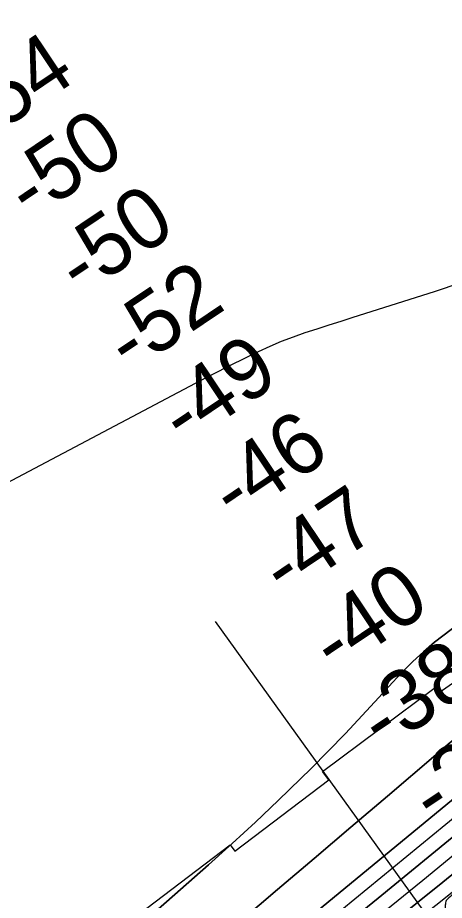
# Model space of a CAD drawing. Extents: x 3445503 to 3483459, y 540493 to 566012.
# Drawn here: x 3455212 to 3455681, y 547772 to 548741 of the extents above; entities that cross this region are included whole.
import ezdxf

# ---------------------------------------------------------------- set-up
doc = ezdxf.new("R2010")
doc.units = 0
for name, color, linetype in [('V-RIVR-EDGE', 7, 'Continuous'), ('V-RIVR-RANG', 7, 'Continuous'), ('V-RRAP-RVMT', 7, 'Continuous'), ('V-TOPO-DPTH', 7, 'Continuous'), ('V-TOPO-MAJR', 7, 'Continuous'), ('V-TOPO-MINR', 7, 'Continuous'), ('V-TOPO-WATR', 7, 'Continuous')]:
    doc.layers.add(name, color=color, linetype=linetype)

msp = doc.modelspace()

# ---------------------------------------------------------------- linework, layer by layer
at = {"layer": 'V-RIVR-EDGE'}
msp.add_spline([(3457863.5, 548983.44), (3457817.44, 548968.66), (3457802.12, 548960.7), (3457767.68, 548948.62), (3457731.48, 548932.03), (3457708.16, 548919.92), (3457702.22, 548907.76), (3457696.63, 548893.52), (3457692.42, 548877.54), (3457690.67, 548875.46), (3457688.95, 548882.77), (3457682.71, 548888), (3457675.41, 548890.1), (3457672.28, 548889.76), (3457669.15, 548886.29), (3457659.75, 548881.8), (3457640.61, 548872.81), (3457631.21, 548868.66), (3457618.34, 548865.21), (3457614.87, 548866.96), (3457612.43, 548865.23), (3457609.99, 548862.8), (3457605.46, 548857.94), (3457597.11, 548854.49), (3457585.62, 548850), (3457581.8, 548851.4), (3457575.19, 548847.94), (3457552.57, 548838.95), (3457523.35, 548829.99), (3457494.47, 548821.37), (3457480.21, 548818.28), (3457458.65, 548813.81), (3457442.3, 548807.59), (3457428.04, 548804.85), (3457409.6, 548800.37), (3457393.95, 548796.94), (3457376.56, 548792.81), (3457356.38, 548788.69), (3457340.38, 548784.9), (3457318.46, 548774.53), (3457282.62, 548763.14), (3457272.18, 548757.26), (3457258.61, 548753.12), (3457234.96, 548746.58), (3457211.64, 548735.51), (3457178.23, 548721.34), (3457160.48, 548713.04), (3457150.74, 548710.28), (3457138.92, 548708.92), (3457133.01, 548708.59), (3457123.96, 548706.52), (3457117, 548701.33), (3457101.68, 548690.94), (3457094.36, 548684), (3457088.79, 548681.58), (3457084.28, 548684.37), (3457080.1, 548683.34), (3457066.53, 548675.73), (3457054, 548670.54), (3457041.13, 548666.4), (3457034.86, 548663.64), (3457030.68, 548658.09), (3457025.11, 548655.32), (3457016.07, 548653.95), (3456990.32, 548646.02), (3456984.06, 548644.3), (3456981.27, 548639.78), (3456973.96, 548638.06), (3456959.69, 548631.49), (3456940.91, 548624.59), (3456930.12, 548621.83), (3456905.41, 548610.42), (3456885.58, 548603.17), (3456858.09, 548591.07), (3456833.02, 548577.58), (3456810.74, 548562.34), (3456791.94, 548553), (3456783.59, 548550.93), (3456781.16, 548549.55), (3456778.37, 548546.43), (3456774.19, 548544.35), (3456766.89, 548543.32), (3456746.35, 548533.29), (3456727.9, 548523.61), (3456715.72, 548515.99), (3456704.94, 548513.93), (3456691.37, 548509.44), (3456678.49, 548503.91), (3456658.31, 548495.62), (3456640.21, 548485.58), (3456625.58, 548475.89), (3456609.92, 548467.23), (3456602.96, 548463.08), (3456594.95, 548459.97), (3456583.81, 548452), (3456563.63, 548444.75), (3456558.75, 548442.33), (3456555.62, 548438.86), (3456546.91, 548431.93), (3456540.64, 548426.73), (3456538.54, 548423.26), (3456538.19, 548420.13), (3456534.36, 548419.8), (3456524.62, 548415.65), (3456518.01, 548413.58), (3456517.3, 548408.02), (3456502.35, 548404.93), (3456494.69, 548400.77), (3456476.93, 548387.61), (3456472.05, 548382.06), (3456471.68, 548376.5), (3456469.94, 548374.41), (3456465.08, 548376.86), (3456461.61, 548378.95), (3456453.6, 548374.46), (3456443.15, 548366.83), (3456436.53, 548360.59), (3456426.08, 548350.19), (3456413.2, 548341.88), (3456403.44, 548333.21), (3456403.08, 548329.39), (3456399.25, 548326.27), (3456385.32, 548316.92), (3456350.52, 548300.66), (3456316.06, 548282.33), (3456280.56, 548264.68), (3456259.31, 548249.09), (3456242.6, 548238.01), (3456225.88, 548225.88), (3456215.09, 548219.31), (3456210.92, 548218.27), (3456207.44, 548216.2), (3456199.77, 548208.91), (3456191.41, 548204.07), (3456188.27, 548196.43), (3456178.85, 548184.63), (3456172.23, 548179.43), (3456163.54, 548177.72), (3456156.58, 548173.56), (3456138.11, 548156.92), (3456111.99, 548136.82), (3456109.19, 548131.27), (3456110.92, 548125.7), (3456109.52, 548121.88), (3456101.86, 548117.38), (3456098.03, 548117.04), (3456095.96, 548120.18), (3456090.39, 548120.19), (3456087.95, 548118.11), (3456087.6, 548114.64), (3456089.67, 548110.81), (3456087.93, 548109.07), (3456081.32, 548104.22), (3456078.87, 548101.1), (3456071.9, 548092.77), (3456063.2, 548086.89), (3456046.14, 548076.5), (3456032.21, 548068.19), (3456019.67, 548059.18), (3456011.66, 548050.86), (3456004, 548047.05), (3455994.6, 548042.21), (3455984.85, 548034.59), (3455970.92, 548024.89), (3455942.36, 548001.67), (3455925.63, 547985.02), (3455888, 547951.4), (3455859.78, 547925.05), (3455831.2, 547897.31), (3455795.68, 547869.93), (3455772.69, 547850.87), (3455751.08, 547830.06), (3455739.93, 547820.36), (3455732.96, 547813.42), (3455726.69, 547806.83), (3455720.08, 547803.37), (3455716.94, 547799.21), (3455712.06, 547794.35), (3455707.19, 547792.63), (3455704.75, 547788.81), (3455704.74, 547786.03), (3455698.83, 547785), (3455689.07, 547777.72), (3455682.8, 547771.83), (3455681.75, 547766.62), (3455680.69, 547760.71), (3455676.86, 547758.63), (3455672.35, 547762.47), (3455669.56, 547759.35), (3455651.44, 547743.05), (3455646.21, 547734.72), (3455640.97, 547725), (3455639.91, 547719.44), (3455637.47, 547716.67), (3455633.3, 547714.59), (3455630.51, 547713.9), (3455628.42, 547711.13), (3455627.72, 547706.96), (3455625.97, 547701.75), (3455612.38, 547691.01), (3455586.95, 547668.82), (3455568.13, 547649.75), (3455560.11, 547641.08), (3455557.32, 547635.17), (3455554.87, 547629.27), (3455551.39, 547626.15), (3455546.52, 547624.77), (3455537.12, 547622.01), (3455533.99, 547619.24), (3455531.89, 547615.77), (3455527.7, 547608.13), (3455520.38, 547600.85), (3455503.66, 547587.68), (3455484.86, 547575.91), (3455468.84, 547563.43), (3455457, 547556.16), (3455434.72, 547543.01), (3455434.37, 547542.31), (3455433.68, 547540.92), (3455432.97, 547536.06), (3455431.22, 547533.63), (3455427.05, 547534.33), (3455422.88, 547532.95), (3455408.6, 547523.95), (3455399.2, 547518.06), (3455395.03, 547516.34), (3455391.54, 547511.83), (3455385.62, 547505.93), (3455380.74, 547503.16), (3455373.09, 547500.05), (3455368.2, 547494.15), (3455365.07, 547491.38), (3455357.76, 547487.58), (3455349.05, 547480.64), (3455342.1, 547480.31), (3455335.84, 547478.94), (3455326.78, 547472.01), (3455309.38, 547463.71), (3455304.16, 547461.98), (3455300.32, 547457.13), (3455295.45, 547452.62), (3455280.83, 547443.96), (3455275.25, 547439.11), (3455272.8, 547433.55), (3455267.93, 547430.09), (3455263.07, 547431.49), (3455257.85, 547431.51), (3455252.98, 547429.78), (3455233.48, 547416.97), (3455216.42, 547405.19), (3455207.71, 547399.3), (3455198.31, 547391.68), (3455194.13, 547387.86), (3455188.19, 547378.84), (3455176, 547368.09), (3455163.46, 547359.43), (3455159.28, 547355.62), (3455156.14, 547351.11), (3455152.66, 547349.03), (3455147.79, 547348.69), (3455143.96, 547345.92), (3455127.59, 547332.06), (3455120.97, 547327.55), (3455111.92, 547319.58), (3455097.98, 547307.8), (3455086.12, 547292.18), (3455071.5, 547281.79), (3455061.39, 547271.73), (3455057.55, 547265.14), (3455056.84, 547257.49), (3455044.3, 547250.22), (3455035.6, 547244.68), (3455007.73, 547222.5), (3454989.62, 547206.21), (3454980.21, 547197.19), (3454971.15, 547190.96), (3454953.72, 547170.14), (3454941.17, 547156.27), (3454928.29, 547146.22), (3454914.36, 547136.17), (3454901.83, 547130.29), (3454894.17, 547128.92), (3454889.64, 547123.02), (3454885.81, 547118.86), (3454878.15, 547115.75), (3454871.54, 547111.6), (3454866.65, 547105.7), (3454853.42, 547094.96), (3454836.01, 547084.92), (3454794.93, 547060.34), (3454775.78, 547046.48), (3454768.12, 547043.37), (3454766.03, 547042.33), (3454765.33, 547039.55), (3454764.63, 547037.82), (3454754.54, 547033.32), (3454745.49, 547027.78), (3454732.6, 547018.78), (3454704.75, 547000.42), (3454687.34, 546990.38), (3454661.57, 546972.72), (3454600.29, 546931.5), (3454566.5, 546905.51), (3454551.88, 546896.16), (3454544.22, 546890.62), (3454540.73, 546885.06), (3454535.49, 546878.47), (3454525.05, 546873.98), (3454519.83, 546871.21), (3454512.52, 546865.67), (3454509.04, 546863.94), (3454507.64, 546859.07), (3454504.15, 546854.22), (3454497.89, 546854.23), (3454492.32, 546851.81), (3454487.45, 546847.65), (3454481.16, 546836.89), (3454475.58, 546829.95), (3454466.53, 546824.76), (3454459.21, 546817.48), (3454445.64, 546809.52), (3454438.31, 546799.1), (3454430.29, 546789.39), (3454418.8, 546782.81), (3454407.67, 546779.71), (3454394.43, 546768.97), (3454388.5, 546760.29), (3454381.88, 546751.62), (3454374.21, 546745.03), (3454365.51, 546742.62), (3454357.85, 546735.69), (3454348.44, 546726.32), (3454339.39, 546720.09), (3454329.98, 546712.12), (3454321.62, 546705.18), (3454311.52, 546695.48), (3454298.63, 546684.73), (3454292.71, 546681.27), (3454288.89, 546681.97), (3454284.36, 546681.29), (3454283.66, 546679.21), (3454283.3, 546671.91), (3454281.2, 546667.39), (3454257.18, 546652.85), (3454236.29, 546638.3), (3454219.56, 546622.35), (3454209.11, 546612.3), (3454190.28, 546592.53), (3454175.65, 546577.96), (3454164.84, 546565.82), (3454160.32, 546563.4), (3454156.15, 546563.76), (3454151.62, 546561.34), (3454148.14, 546559.61), (3454133.51, 546546.09), (3454102.5, 546519.05), (3454096.23, 546515.94), (3454092.4, 546512.12), (3454086.13, 546505.53), (3454079.15, 546495.81), (3454067.99, 546482.98), (3454055.1, 546469.8), (3454040.81, 546455.93), (3454027.93, 546447.27), (3454012.95, 546435.14), (3453974.28, 546400.13), (3453969.39, 546393.53), (3453968.69, 546390.41), (3453968.33, 546386.93), (3453963.45, 546381.03), (3453948.12, 546364.04), (3453931.73, 546346.7), (3453925.47, 546344.63), (3453916.77, 546339.09), (3453902.84, 546331.13), (3453885.77, 546314.13), (3453868.69, 546296.1), (3453855.43, 546277.01), (3453829.27, 546239.88), (3453825.07, 546231.9), (3453825.07, 546228.77), (3453825.06, 546225.99), (3453824.36, 546224.6), (3453819.15, 546224.26), (3453815.32, 546222.88), (3453811.13, 546217.68), (3453801.36, 546202.06), (3453785.31, 546179.15), (3453759.16, 546146.89), (3453726.4, 546113.6), (3453681.81, 546074.77), (3453648.37, 546047.39), (3453614.59, 546023.84), (3453592.32, 546013.12), (3453571.08, 545999.61), (3453548.78, 545978.11), (3453537.97, 545968.06), (3453529.26, 545959.39), (3453525.44, 545959.05), (3453521.6, 545955.58), (3453517.42, 545950.73), (3453513.59, 545946.22), (3453508.71, 545944.14), (3453506.62, 545941.02), (3453505.22, 545937.89), (3453495.82, 545932.01), (3453490.94, 545926.46), (3453484.31, 545918.13), (3453481.19, 545917.79), (3453476.66, 545916.06), (3453470.04, 545909.82), (3453466.25, 545904.68)], degree=3, dxfattribs=at)
at = {"layer": 'V-RIVR-RANG'}
msp.add_line((3455826.74, 547526.64), (3455429.18, 548078.32), dxfattribs=at)
at = {"layer": 'V-RRAP-RVMT'}
for p, q in [((3455674.82, 548000.19), (3455792.37, 548082.35)), ((3455546.91, 547913.53), (3455670.75, 548005.67)), ((3455670.75, 548005.67), (3455674.82, 548000.19)), ((3455553.75, 547904.34), (3455546.91, 547913.53)), ((3455450.6, 547825.86), (3455553.75, 547904.34)), ((3455321.66, 547739.15), (3455445.16, 547833.06)), ((3455445.16, 547833.06), (3455450.6, 547825.86))]:
    msp.add_line(p, q, dxfattribs=at)
at = {"layer": 'V-TOPO-DPTH'}
for points in [[(3456856.6, 548740.67), (3456268.73, 548406.59), (3456247.79, 548392.03), (3456227.02, 548377.24), (3456206.5, 548362.08), (3455712.34, 547966.57), (3455698.61, 547955.04), (3455684.92, 547943.46), (3455671.26, 547931.85), (3455618.12, 547886.49), (3455577.89, 547852.2), (3455537.62, 547817.95), (3455497.3, 547783.76), (3455456.94, 547749.62), (3455214.72, 547545.03), (3455182.45, 547518.06), (3455149.99, 547491.33), (3455117.26, 547464.94), (3455084.33, 547438.79), (3455046.17, 547408.8), (3454993.9, 547367.98), (3454941.46, 547327.38), (3454918.49, 547309.76)], [(3456856.6, 548740.67), (3456268.73, 548406.59), (3456247.79, 548392.03), (3456227.02, 548377.24), (3456206.5, 548362.08), (3455712.34, 547966.57), (3455698.61, 547955.04), (3455684.92, 547943.46), (3455671.26, 547931.85), (3455618.12, 547886.49), (3455577.89, 547852.2), (3455537.62, 547817.95), (3455497.3, 547783.76), (3455456.94, 547749.62), (3455214.72, 547545.03), (3455182.45, 547518.06), (3455149.99, 547491.33), (3455117.26, 547464.94), (3455084.33, 547438.79), (3455046.17, 547408.8), (3454993.9, 547367.98), (3454941.46, 547327.38), (3454918.49, 547309.76)], [(3455249.33, 547659.48), (3455421.6, 547811.2), (3455447.45, 547834.36), (3455473.04, 547857.81), (3455498.22, 547881.68), (3455523.14, 547905.85), (3455533.99, 547916.56), (3455553.11, 547935.75), (3455572, 547955.16), (3455590.53, 547974.9), (3455608.84, 547994.86), (3455623.66, 548011.31), (3455634.64, 548022.96), (3455645.94, 548034.26), (3455657.73, 548045.04), (3455669.86, 548055.48), (3456187.62, 548449.08), (3456215.38, 548468.62), (3456243.11, 548488.2), (3456319.08, 548541.99), (3456382.52, 548587.52), (3456445.56, 548633.6), (3456508, 548680.48), (3456570.03, 548727.91)], [(3456570.03, 548727.91), (3456508, 548680.48), (3456445.56, 548633.6), (3456382.52, 548587.52), (3456319.08, 548541.99), (3456243.11, 548488.2), (3456215.38, 548468.62), (3456187.62, 548449.08), (3455669.86, 548055.48), (3455657.73, 548045.04), (3455645.94, 548034.26), (3455634.64, 548022.96), (3455623.66, 548011.31), (3455608.84, 547994.86), (3455590.53, 547974.9), (3455572, 547955.16), (3455553.11, 547935.75), (3455533.99, 547916.56), (3455523.14, 547905.85), (3455498.22, 547881.68), (3455473.04, 547857.81), (3455447.45, 547834.36), (3455421.6, 547811.2), (3455249.33, 547659.48)], [(3456887.15, 548729.97), (3456251.76, 548335.86), (3456250.94, 548335.31), (3456248.53, 548333.61), (3456244.09, 548330.33), (3456241.1, 548328.09), (3456238.13, 548325.81), (3456235.19, 548323.5), (3456232.27, 548321.15), (3456209.81, 548302.85), (3456195.66, 548291.35), (3456181.51, 548279.87), (3456167.33, 548268.41), (3456153.14, 548256.96), (3455823.07, 547991.16), (3455806.97, 547978.17), (3455790.88, 547965.17), (3455774.82, 547952.13), (3455758.77, 547939.08), (3455742.75, 547926.01), (3455726.73, 547912.91), (3455710.74, 547899.8), (3455694.75, 547886.67), (3455356.77, 547608.66)], [(3455356.77, 547608.66), (3455694.75, 547886.67), (3455710.74, 547899.8), (3455726.73, 547912.91), (3455742.75, 547926.01), (3455758.77, 547939.08), (3455774.82, 547952.13), (3455790.88, 547965.17), (3455806.97, 547978.17), (3455823.07, 547991.16), (3456153.14, 548256.96), (3456167.33, 548268.41), (3456181.51, 548279.87), (3456195.66, 548291.35), (3456209.81, 548302.85), (3456232.27, 548321.15), (3456235.19, 548323.5), (3456238.13, 548325.81), (3456241.1, 548328.09), (3456244.09, 548330.33), (3456248.53, 548333.61), (3456250.94, 548335.31), (3456251.76, 548335.86), (3456887.15, 548729.97)], [(3455539.36, 547718.68), (3455607.82, 547774.46), (3455703.41, 547852.68), (3455723.95, 547869.49), (3455744.5, 547886.3), (3455765.05, 547903.1), (3455785.61, 547919.9), (3455844.79, 547968.27), (3455895.2, 548008.91), (3455945.96, 548049.11), (3455997.24, 548088.64), (3456048.87, 548127.73), (3456227.26, 548260.95), (3456249.85, 548277.51), (3456272.62, 548293.81), (3456295.66, 548309.72), (3456318.89, 548325.36), (3456949.78, 548713.88)], [(3456949.78, 548713.88), (3456318.89, 548325.36), (3456295.66, 548309.72), (3456272.62, 548293.81), (3456249.85, 548277.51), (3456227.26, 548260.95), (3456048.87, 548127.73), (3455997.24, 548088.64), (3455945.96, 548049.11), (3455895.2, 548008.91), (3455844.79, 547968.27), (3455785.61, 547919.9), (3455765.05, 547903.1), (3455744.5, 547886.3), (3455723.95, 547869.49), (3455703.41, 547852.68), (3455607.82, 547774.46), (3455539.36, 547718.68)], [(3454919.06, 547191.84), (3454965.95, 547228.53), (3455040.68, 547286.89), (3455148.1, 547370.65), (3455178.59, 547394.48), (3455209.03, 547418.37), (3455239.4, 547442.34), (3455269.74, 547466.37), (3455595.27, 547724.91), (3455623.23, 547747.21), (3455651.15, 547769.57), (3455678.98, 547792.04), (3455706.76, 547814.57), (3455734.49, 547837.16), (3455762.2, 547859.77), (3455789.89, 547882.42), (3455817.57, 547905.08), (3456265.35, 548253.11), (3456276.04, 548260.48), (3456286.85, 548267.67), (3456297.83, 548274.6), (3456308.92, 548281.35), (3456668.27, 548494.2)], [(3456668.27, 548494.2), (3456308.92, 548281.35), (3456297.83, 548274.6), (3456286.85, 548267.67), (3456276.04, 548260.48), (3456265.35, 548253.11), (3455817.57, 547905.08), (3455789.89, 547882.42), (3455762.2, 547859.77), (3455734.49, 547837.16), (3455706.76, 547814.57), (3455678.98, 547792.04), (3455651.15, 547769.57), (3455623.23, 547747.21), (3455595.27, 547724.91), (3455269.74, 547466.37), (3455239.4, 547442.34), (3455209.03, 547418.37), (3455178.59, 547394.48), (3455148.1, 547370.65), (3455040.68, 547286.89), (3454965.95, 547228.53), (3454919.06, 547191.84)]]:
    msp.add_lwpolyline(points, dxfattribs=at)
at = {"layer": 'V-TOPO-MAJR'}
msp.add_lwpolyline([(3455167.25, 548213.26), (3455419.73, 548346.46), (3455426.21, 548349.84), (3455432.71, 548353.18), (3455439.24, 548356.46), (3455445.79, 548359.7), (3455476.62, 548374.78), (3455489.15, 548380.59), (3455501.84, 548386.03), (3455514.74, 548390.92), (3455527.79, 548395.45), (3455540.96, 548399.69), (3455554.13, 548403.92), (3455567.31, 548408.11), (3455580.5, 548412.29), (3455669.92, 548440.49), (3455727.26, 548460.11)], dxfattribs=at)
at = {"layer": 'V-TOPO-MINR'}
for points in [[(3454918.49, 547309.76), (3454941.46, 547327.38), (3454993.9, 547367.98), (3455046.17, 547408.8), (3455084.33, 547438.79), (3455117.26, 547464.94), (3455149.99, 547491.33), (3455182.45, 547518.06), (3455214.72, 547545.03), (3455456.94, 547749.62), (3455497.3, 547783.76), (3455537.62, 547817.95), (3455577.89, 547852.2), (3455618.12, 547886.49), (3455671.26, 547931.85), (3455684.92, 547943.46), (3455698.61, 547955.04), (3455712.34, 547966.57), (3456206.5, 548362.08), (3456227.02, 548377.24), (3456247.79, 548392.03), (3456268.73, 548406.59), (3456856.6, 548740.67)], [(3455249.33, 547659.48), (3455421.6, 547811.2), (3455447.45, 547834.36), (3455473.04, 547857.81), (3455498.22, 547881.68), (3455523.14, 547905.85), (3455533.99, 547916.56), (3455553.11, 547935.75), (3455572, 547955.16), (3455590.53, 547974.9), (3455608.84, 547994.86), (3455623.66, 548011.31), (3455634.64, 548022.96), (3455645.94, 548034.26), (3455657.73, 548045.04), (3455669.86, 548055.48), (3456187.62, 548449.08), (3456215.38, 548468.62), (3456243.11, 548488.2), (3456319.08, 548541.99), (3456382.52, 548587.52), (3456445.56, 548633.6), (3456508, 548680.48), (3456570.03, 548727.91)], [(3455356.77, 547608.66), (3455694.75, 547886.67), (3455710.74, 547899.8), (3455726.73, 547912.91), (3455742.75, 547926.01), (3455758.77, 547939.08), (3455774.82, 547952.13), (3455790.88, 547965.17), (3455806.97, 547978.17), (3455823.07, 547991.16), (3456153.14, 548256.96), (3456167.33, 548268.41), (3456181.51, 548279.87), (3456195.66, 548291.35), (3456209.81, 548302.85), (3456232.27, 548321.15), (3456235.19, 548323.5), (3456238.13, 548325.81), (3456241.1, 548328.09), (3456244.09, 548330.33), (3456248.53, 548333.61), (3456250.94, 548335.31), (3456251.76, 548335.86), (3456887.15, 548729.97)], [(3455482.15, 547691.66), (3455682.18, 547855.79), (3455708.9, 547877.69), (3455735.63, 547899.59), (3455762.39, 547921.46), (3455789.15, 547943.31), (3455801.99, 547953.78), (3455835.28, 547980.73), (3455868.72, 548007.5), (3455902.36, 548034.02), (3455936.14, 548060.36), (3456217.93, 548278.3), (3456240.22, 548295.27), (3456262.66, 548312.02), (3456285.36, 548328.43), (3456308.21, 548344.62), (3456331.28, 548360.52), (3456354.45, 548376.26), (3456377.79, 548391.75), (3456401.24, 548407.07), (3456916.3, 548730.55)], [(3455539.36, 547718.68), (3455607.82, 547774.46), (3455703.41, 547852.68), (3455723.95, 547869.49), (3455744.5, 547886.3), (3455765.05, 547903.1), (3455785.61, 547919.9), (3455844.79, 547968.27), (3455895.2, 548008.91), (3455945.96, 548049.11), (3455997.24, 548088.64), (3456048.87, 548127.73), (3456227.26, 548260.95), (3456249.85, 548277.51), (3456272.62, 548293.81), (3456295.66, 548309.72), (3456318.89, 548325.36), (3456949.78, 548713.88)], [(3454919.17, 547167.8), (3455096.07, 547308.26), (3455116.58, 547324.54), (3455137.09, 547340.8), (3455157.62, 547357.05), (3455178.15, 547373.3), (3455198.67, 547389.55), (3455219.18, 547405.82), (3455239.67, 547422.11), (3455260.14, 547438.43), (3455729.68, 547813.04), (3455736.61, 547818.58), (3455743.52, 547824.14), (3455750.43, 547829.71), (3455757.32, 547835.29), (3455764.2, 547840.88), (3455771.08, 547846.49), (3455777.95, 547852.1), (3455784.81, 547857.72), (3456285.79, 548254.07), (3456292.05, 548258.12), (3456298.42, 548261.98), (3456304.87, 548265.74), (3456952.88, 548630.57)], [(3455608.64, 547755.05), (3455656.94, 547794.3), (3455704.65, 547833.24), (3455729.01, 547853.13), (3455753.36, 547873.02), (3455777.71, 547892.93), (3455802.04, 547912.84), (3455897.28, 547990.79), (3455959.61, 548040.89), (3456150.59, 548186.02), (3456248.15, 548256.77), (3456264.24, 548268.18), (3456280.48, 548279.37), (3456296.95, 548290.21), (3456313.58, 548300.83), (3456444.85, 548382.75), (3456525.49, 548432.18)]]:
    msp.add_lwpolyline(points, dxfattribs=at)
at = {"layer": 'V-TOPO-WATR'}
msp.add_lwpolyline([(3454919.06, 547191.84), (3454965.95, 547228.53), (3455040.68, 547286.89), (3455148.1, 547370.65), (3455178.59, 547394.48), (3455209.03, 547418.37), (3455239.4, 547442.34), (3455269.74, 547466.37), (3455595.27, 547724.91), (3455623.23, 547747.21), (3455651.15, 547769.57), (3455678.98, 547792.04), (3455706.76, 547814.57), (3455734.49, 547837.16), (3455762.2, 547859.77), (3455789.89, 547882.42), (3455817.57, 547905.08), (3456265.35, 548253.11), (3456276.04, 548260.48), (3456286.85, 548267.67), (3456297.83, 548274.6), (3456308.92, 548281.35), (3456668.27, 548494.2)], dxfattribs=at)

# ---------------------------------------------------------------- texts
at = {"layer": 'V-RIVR-RANG'}
for s, p in [('-54', (3455170.74, 548601.26)), ('-50', (3455225.4, 548517.51)), ('-50', (3455280.93, 548434.35)), ('-52', (3455334.93, 548350.15)), ('-49', (3455394.63, 548269.79)), ('-46', (3455449.94, 548186.48)), ('-47', (3455505.25, 548103.16)), ('-40', (3455560.35, 548019.71)), ('-38', (3455613.04, 547934.64)), ('-24', (3455669.67, 547852.21))]:
    msp.add_text(s, height=67, rotation=33.87589, dxfattribs=at).set_placement(p)

doc.saveas('drawing.dxf')
